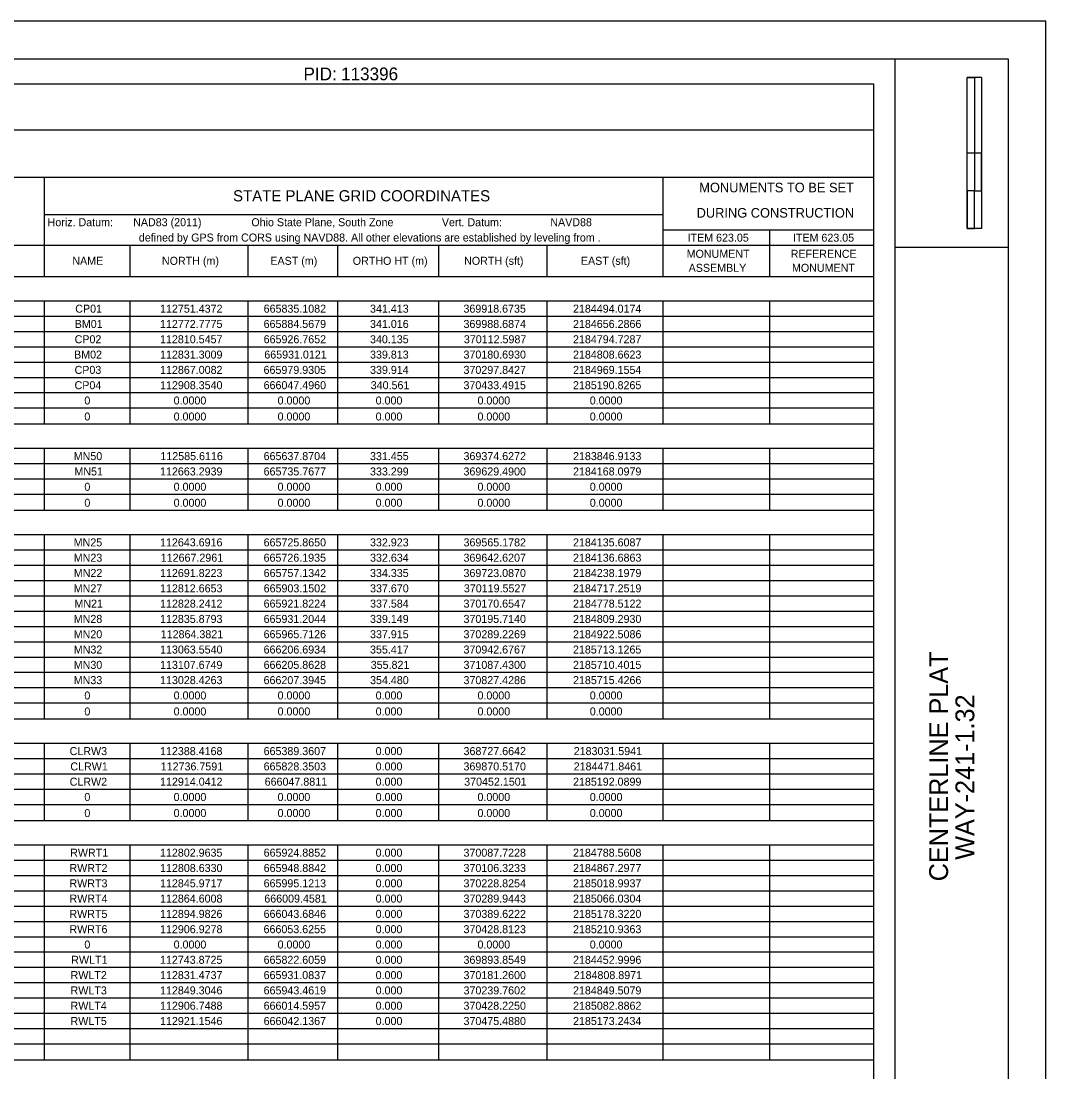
# Model space of a CAD drawing. Extents: x 0 to 680, y 0 to 440.
# Drawn here: x 408.1 to 680, y 161.3 to 440 of the extents above; entities that cross this region are included whole.
import ezdxf

# ---------------------------------------------------------------- set-up
doc = ezdxf.new("R2010")
doc.units = 0
for name, color, linetype in [('SH_Border', 7, 'Continuous'), ('SH_Cut_Line', 7, 'Continuous'), ('SH_Data', 7, 'Continuous'), ('SH_Text', 7, 'Continuous')]:
    doc.layers.add(name, color=color, linetype=linetype)

msp = doc.modelspace()

# ---------------------------------------------------------------- linework, layer by layer
at = {"layer": 'SH_Border'}
for p, q in [((640, 10), (640, 430)), ((640, 380), (670, 380))]:
    msp.add_line(p, q, dxfattribs=at)
msp.add_lwpolyline([(30, 430), (670, 430), (670, 10), (30, 10)], close=True, dxfattribs=at)
at = {"layer": 'SH_Cut_Line'}
msp.add_lwpolyline([(0, 0), (680, 0), (680, 440), (0, 440)], close=True, dxfattribs=at)
at = {"layer": 'SH_Data'}
for p, q in [((659.13, 385), (659.13, 425)), ((662.88, 425), (659.13, 425)), ((659.13, 405), (659.13, 425)), ((659.13, 425), (661, 425)), ((661, 425), (661.02, 425)), ((661.02, 425), (661.02, 405)), ((662.88, 425), (662.88, 385)), ((661.02, 405), (659.13, 405)), ((662.87, 405), (661, 405)), ((661, 405), (661, 395)), ((662.87, 395), (662.87, 405)), ((661, 395), (659.13, 395)), ((659.13, 395), (659.13, 385)), ((661, 395), (662.87, 395)), ((661, 385), (661, 395)), ((662.88, 385), (659.13, 385)), ((659.13, 385), (661, 385))]:
    msp.add_line(p, q, dxfattribs=at)
at = {"layer": 'SH_Text'}
for p, q in [((231.79, 423.36), (436.91, 423.36)), ((436.91, 423.36), (634.27, 423.36)), ((634.27, 423.36), (634.27, 398.64)), ((259.46, 411.19), (436.91, 411.19)), ((436.91, 411.19), (634.27, 411.19)), ((259.46, 398.64), (436.91, 398.64)), ((414.22, 398.64), (414.22, 380.57)), ((436.91, 398.64), (634.27, 398.64)), ((578.38, 398.64), (578.38, 380.57)), ((634.27, 398.64), (634.27, 380.57)), ((414.22, 388.68), (436.91, 388.68)), ((436.91, 388.68), (578.38, 388.68)), ((578.38, 384.62), (634.27, 384.62)), ((606.61, 384.62), (606.61, 380.57)), ((231.79, 380.57), (436.91, 380.57)), ((414.22, 380.57), (414.22, 372.27)), ((436.91, 380.57), (634.27, 380.57)), ((436.91, 380.57), (436.91, 372.27)), ((468.27, 380.57), (468.27, 372.27)), ((492.06, 380.57), (492.06, 372.27)), ((518.81, 380.57), (518.81, 372.27)), ((547.58, 380.57), (547.58, 372.27)), ((578.38, 380.57), (578.38, 372.27)), ((606.61, 380.57), (606.61, 372.27)), ((634.27, 380.57), (634.27, 349.58)), ((231.79, 372.27), (436.91, 372.27)), ((436.91, 372.27), (634.27, 372.27)), ((231.79, 365.81), (436.91, 365.81)), ((414.22, 365.81), (414.22, 349.58)), ((436.91, 365.81), (634.27, 365.81)), ((436.91, 365.81), (436.91, 349.58)), ((468.27, 365.81), (468.27, 349.58)), ((492.06, 365.81), (492.06, 349.58)), ((518.81, 365.81), (518.81, 349.58)), ((547.58, 365.81), (547.58, 349.58)), ((578.38, 365.81), (578.38, 349.58)), ((606.61, 365.81), (606.61, 349.58)), ((231.79, 361.75), (436.91, 361.75)), ((436.91, 361.75), (634.27, 361.75)), ((231.79, 357.69), (436.91, 357.69)), ((436.91, 357.69), (634.27, 357.69)), ((231.79, 353.64), (436.91, 353.64)), ((436.91, 353.64), (634.27, 353.64)), ((231.79, 349.58), (436.91, 349.58)), ((414.22, 349.58), (414.22, 345.52)), ((436.91, 349.58), (634.27, 349.58)), ((436.91, 349.58), (436.91, 345.52)), ((468.27, 349.58), (468.27, 345.52)), ((492.06, 349.58), (492.06, 345.52)), ((518.81, 349.58), (518.81, 345.52)), ((547.58, 349.58), (547.58, 345.52)), ((578.38, 349.58), (578.38, 345.52)), ((606.61, 349.58), (606.61, 345.52)), ((634.27, 349.58), (634.27, 345.52)), ((231.79, 345.52), (436.91, 345.52)), ((414.22, 345.52), (414.22, 333.16)), ((436.91, 345.52), (634.27, 345.52)), ((436.91, 345.52), (436.91, 333.16)), ((468.27, 345.52), (468.27, 333.16)), ((492.06, 345.52), (492.06, 333.16)), ((518.81, 345.52), (518.81, 333.16)), ((547.58, 345.52), (547.58, 333.16)), ((578.38, 345.52), (578.38, 333.16)), ((606.61, 345.52), (606.61, 333.16)), ((634.27, 345.52), (634.27, 267.31)), ((231.79, 341.46), (436.91, 341.46)), ((436.91, 341.46), (634.27, 341.46)), ((231.79, 337.4), (436.91, 337.4)), ((436.91, 337.4), (634.27, 337.4)), ((231.79, 333.16), (436.91, 333.16)), ((436.91, 333.16), (634.27, 333.16)), ((231.79, 326.71), (436.91, 326.71)), ((414.22, 326.71), (414.22, 310.29)), ((436.91, 326.71), (634.27, 326.71)), ((436.91, 326.71), (436.91, 310.29)), ((468.27, 326.71), (468.27, 310.29)), ((492.06, 326.71), (492.06, 310.29)), ((518.81, 326.71), (518.81, 310.29)), ((547.58, 326.71), (547.58, 310.29)), ((578.38, 326.71), (578.38, 310.29)), ((606.61, 326.71), (606.61, 310.29)), ((231.79, 322.65), (436.91, 322.65)), ((436.91, 322.65), (634.27, 322.65)), ((231.79, 318.59), (436.91, 318.59)), ((436.91, 318.59), (634.27, 318.59)), ((231.79, 314.53), (436.91, 314.53)), ((436.91, 314.53), (634.27, 314.53)), ((231.79, 310.29), (436.91, 310.29)), ((436.91, 310.29), (634.27, 310.29)), ((231.79, 303.83), (436.91, 303.83)), ((414.22, 303.83), (414.22, 267.31)), ((436.91, 303.83), (634.27, 303.83)), ((436.91, 303.83), (436.91, 267.31)), ((468.27, 303.83), (468.27, 267.31)), ((492.06, 303.83), (492.06, 267.31)), ((518.81, 303.83), (518.81, 267.31)), ((547.58, 303.83), (547.58, 267.31)), ((578.38, 303.83), (578.38, 267.31)), ((606.61, 303.83), (606.61, 267.31)), ((231.79, 299.78), (436.91, 299.78)), ((436.91, 299.78), (634.27, 299.78)), ((231.79, 295.72), (436.91, 295.72)), ((436.91, 295.72), (634.27, 295.72)), ((231.79, 291.66), (436.91, 291.66)), ((436.91, 291.66), (634.27, 291.66)), ((231.79, 287.6), (436.91, 287.6)), ((436.91, 287.6), (634.27, 287.6)), ((231.79, 283.54), (436.91, 283.54)), ((436.91, 283.54), (634.27, 283.54)), ((231.79, 279.49), (436.91, 279.49)), ((436.91, 279.49), (634.27, 279.49)), ((231.79, 275.43), (436.91, 275.43)), ((436.91, 275.43), (634.27, 275.43)), ((231.79, 271.37), (436.91, 271.37)), ((436.91, 271.37), (634.27, 271.37)), ((231.79, 267.31), (436.91, 267.31)), ((414.22, 267.31), (414.22, 263.25)), ((436.91, 267.31), (634.27, 267.31)), ((436.91, 267.31), (436.91, 263.25)), ((468.27, 267.31), (468.27, 263.25)), ((492.06, 267.31), (492.06, 263.25)), ((518.81, 267.31), (518.81, 263.25)), ((547.58, 267.31), (547.58, 263.25)), ((578.38, 267.31), (578.38, 263.25)), ((606.61, 267.31), (606.61, 263.25)), ((634.27, 267.31), (634.27, 263.25)), ((231.79, 263.25), (436.91, 263.25)), ((414.22, 263.25), (414.22, 254.95)), ((436.91, 263.25), (634.27, 263.25)), ((436.91, 263.25), (436.91, 254.95)), ((468.27, 263.25), (468.27, 254.95)), ((492.06, 263.25), (492.06, 254.95)), ((518.81, 263.25), (518.81, 254.95)), ((547.58, 263.25), (547.58, 254.95)), ((578.38, 263.25), (578.38, 254.95)), ((606.61, 263.25), (606.61, 254.95)), ((634.27, 263.25), (634.27, 240.38)), ((231.79, 259.2), (436.91, 259.2)), ((436.91, 259.2), (634.27, 259.2)), ((231.79, 254.95), (436.91, 254.95)), ((436.91, 254.95), (634.27, 254.95)), ((231.79, 248.5), (436.91, 248.5)), ((414.22, 248.5), (414.22, 240.38)), ((436.91, 248.5), (634.27, 248.5)), ((436.91, 248.5), (436.91, 240.38)), ((468.27, 248.5), (468.27, 240.38)), ((492.06, 248.5), (492.06, 240.38)), ((518.81, 248.5), (518.81, 240.38)), ((547.58, 248.5), (547.58, 240.38)), ((578.38, 248.5), (578.38, 240.38)), ((606.61, 248.5), (606.61, 240.38)), ((231.79, 244.44), (436.91, 244.44)), ((436.91, 244.44), (634.27, 244.44)), ((231.79, 240.38), (436.91, 240.38)), ((414.22, 240.38), (414.22, 236.32)), ((436.91, 240.38), (634.27, 240.38)), ((436.91, 240.38), (436.91, 236.32)), ((468.27, 240.38), (468.27, 236.32)), ((492.06, 240.38), (492.06, 236.32)), ((518.81, 240.38), (518.81, 236.32)), ((547.58, 240.38), (547.58, 236.32)), ((578.38, 240.38), (578.38, 236.32)), ((606.61, 240.38), (606.61, 236.32)), ((634.27, 240.38), (634.27, 236.32)), ((231.79, 236.32), (436.91, 236.32)), ((414.22, 236.32), (414.22, 232.26)), ((436.91, 236.32), (634.27, 236.32)), ((436.91, 236.32), (436.91, 232.26)), ((468.27, 236.32), (468.27, 232.26)), ((492.06, 236.32), (492.06, 232.26)), ((518.81, 236.32), (518.81, 232.26)), ((547.58, 236.32), (547.58, 232.26)), ((578.38, 236.32), (578.38, 232.26)), ((606.61, 236.32), (606.61, 232.26)), ((634.27, 236.32), (634.27, 232.26)), ((231.79, 232.26), (436.91, 232.26)), ((414.22, 232.26), (414.22, 228.02)), ((436.91, 232.26), (634.27, 232.26)), ((436.91, 232.26), (436.91, 228.02)), ((468.27, 232.26), (468.27, 228.02)), ((492.06, 232.26), (492.06, 228.02)), ((518.81, 232.26), (518.81, 228.02)), ((547.58, 232.26), (547.58, 228.02)), ((578.38, 232.26), (578.38, 228.02)), ((606.61, 232.26), (606.61, 228.02)), ((634.27, 232.26), (634.27, 228.02)), ((231.79, 228.02), (436.91, 228.02)), ((436.91, 228.02), (634.27, 228.02)), ((634.27, 228.02), (634.27, 217.51)), ((231.79, 221.57), (436.91, 221.57)), ((414.22, 221.57), (414.22, 217.51)), ((436.91, 221.57), (634.27, 221.57)), ((436.91, 221.57), (436.91, 217.51)), ((468.27, 221.57), (468.27, 217.51)), ((492.06, 221.57), (492.06, 217.51)), ((518.81, 221.57), (518.81, 217.51)), ((547.58, 221.57), (547.58, 217.51)), ((578.38, 221.57), (578.38, 217.51)), ((606.61, 221.57), (606.61, 217.51)), ((231.79, 217.51), (436.91, 217.51)), ((414.22, 217.51), (414.22, 164.57)), ((436.91, 217.51), (634.27, 217.51)), ((436.91, 217.51), (436.91, 164.57)), ((468.27, 217.51), (468.27, 164.57)), ((492.06, 217.51), (492.06, 164.57)), ((518.81, 217.51), (518.81, 164.57)), ((547.58, 217.51), (547.58, 164.57)), ((578.38, 217.51), (578.38, 164.57)), ((606.61, 217.51), (606.61, 164.57)), ((634.27, 217.51), (634.27, 113.48)), ((231.79, 213.45), (436.91, 213.45)), ((436.91, 213.45), (634.27, 213.45)), ((231.79, 209.39), (436.91, 209.39)), ((436.91, 209.39), (634.27, 209.39)), ((231.79, 205.33), (436.91, 205.33)), ((436.91, 205.33), (634.27, 205.33)), ((231.79, 201.28), (436.91, 201.28)), ((436.91, 201.28), (634.27, 201.28)), ((231.79, 197.22), (436.91, 197.22)), ((436.91, 197.22), (634.27, 197.22)), ((231.79, 193.16), (436.91, 193.16)), ((436.91, 193.16), (634.27, 193.16)), ((231.79, 189.1), (436.91, 189.1)), ((436.91, 189.1), (634.27, 189.1)), ((231.79, 185.04), (436.91, 185.04)), ((436.91, 185.04), (634.27, 185.04)), ((231.79, 180.99), (436.91, 180.99)), ((436.91, 180.99), (634.27, 180.99)), ((231.79, 176.93), (436.91, 176.93)), ((436.91, 176.93), (634.27, 176.93)), ((231.79, 172.87), (436.91, 172.87)), ((436.91, 172.87), (634.27, 172.87)), ((231.79, 168.81), (436.91, 168.81)), ((436.91, 168.81), (634.27, 168.81)), ((231.79, 164.57), (436.91, 164.57)), ((436.91, 164.57), (634.27, 164.57))]:
    msp.add_line(p, q, dxfattribs=at)

# ---------------------------------------------------------------- texts
at = {"layer": 'SH_Data'}
for s, p in [('CENTERLINE PLAT', (654.02, 211.9)), ('WAY-241-1.32', (660.98, 217.6))]:
    msp.add_text(s, height=5, rotation=90, dxfattribs=at).set_placement(p)
at = {"layer": 'SH_Text'}
for s, height, p in [('PID:', 3.394, (483.02, 424.28)), ('113396', 3.394, (492.98, 424.28)), ('  MONUMENTS TO BE SET', 2.5455, (586.12, 394.58)), ('STATE PLANE GRID COORDINATES', 2.9697, (464.34, 392.18)), (' DURING CONSTRUCTION', 2.5455, (586.36, 387.87)), ('Horiz. Datum:', 2.1212, (415.14, 385.59)), ('NAD83 (2011)', 2.1212, (437.83, 385.59)), ('Ohio State Plane, South Zone', 2.1212, (469.19, 385.59)), ('Vert. Datum:', 2.1212, (519.73, 385.59)), ('NAVD88', 2.121, (548.5, 385.59)), (' defined by GPS from CORS using NAVD88. All other elevations are established by leveling from .', 2.1212, (438.56, 381.53)), ('ITEM 623.05', 2.1212, (584.91, 381.49)), ('ITEM 623.05', 2.1212, (612.86, 381.49)), ('MONUMENT ', 2.121, (584.67, 377.21)), ('REFERENCE ', 2.121, (612.28, 377.21)), ('NAME', 2.121, (421.7, 375.36)), ('NORTH (m)', 2.121, (445.47, 375.36)), ('EAST (m)', 2.121, (474.23, 375.36)), ('ORTHO HT (m)', 2.1212, (496.09, 375.36)), ('NORTH (sft)', 2.1212, (525.63, 375.36)), ('EAST (sft)', 2.121, (556.61, 375.36)), ('ASSEMBLY', 2.121, (585.2, 373.5)), ('MONUMENT', 2.121, (612.61, 373.5)), ('CP01', 2.121, (422.47, 362.67)), ('112751.4372', 2.1212, (444.97, 362.67)), ('665835.1082', 2.1212, (472.45, 362.67)), ('341.413', 2.121, (500.67, 362.67)), ('369918.6735', 2.1212, (525.46, 362.67)), ('2184494.0174', 2.1212, (554.52, 362.67)), ('BM01', 2.121, (422.33, 358.62)), ('112772.7775', 2.1212, (444.95, 358.62)), ('665884.5679', 2.1212, (472.44, 358.62)), ('341.016', 2.121, (500.67, 358.62)), ('369988.6874', 2.1212, (525.47, 358.62)), ('2184656.2866', 2.1212, (554.52, 358.62)), ('CP02', 2.121, (422.3, 354.56)), ('112810.5457', 2.1212, (444.96, 354.56)), ('665926.7652', 2.1212, (472.45, 354.56)), ('340.135', 2.121, (500.67, 354.56)), ('370112.5987', 2.1212, (525.57, 354.56)), ('2184794.7287', 2.1212, (554.52, 354.56)), ('BM02', 2.121, (422.15, 350.5)), ('112831.3009', 2.1212, (444.96, 350.5)), ('665931.0121', 2.1212, (472.62, 350.5)), ('339.813', 2.121, (500.67, 350.5)), ('370180.6930', 2.1212, (525.47, 350.5)), ('2184808.6623', 2.1212, (554.52, 350.5)), ('CP03', 2.121, (422.29, 346.44)), ('112867.0082', 2.1212, (444.97, 346.44)), ('665979.9305', 2.1212, (472.43, 346.44)), ('339.914', 2.121, (500.68, 346.44)), ('370297.8427', 2.1212, (525.47, 346.44)), ('2184969.1554', 2.1212, (554.52, 346.44)), ('CP04', 2.121, (422.29, 342.38)), ('112908.3540', 2.1212, (444.97, 342.38)), ('666047.4960', 2.1212, (472.44, 342.38)), ('340.561', 2.121, (500.86, 342.38)), ('370433.4915', 2.1212, (525.46, 342.38)), ('2185190.8265', 2.1212, (554.51, 342.38)), ('0', 2.12, (424.89, 338.33)), ('0.0000', 2.121, (448.57, 338.33)), ('0.0000', 2.121, (476.15, 338.33)), ('0.000', 2.121, (502.16, 338.33)), ('0.0000', 2.121, (529.18, 338.33)), ('0.0000', 2.121, (558.97, 338.33)), ('0', 2.12, (424.89, 334.08)), ('0.0000', 2.121, (448.57, 334.08)), ('0.0000', 2.121, (476.15, 334.08)), ('0.000', 2.121, (502.16, 334.08)), ('0.0000', 2.121, (529.18, 334.08)), ('0.0000', 2.121, (558.97, 334.08)), ('MN50', 2.121, (422.07, 323.57)), ('112585.6116', 2.1212, (445.06, 323.57)), ('665637.8704', 2.1212, (472.44, 323.57)), ('331.455', 2.121, (500.67, 323.57)), ('369374.6272', 2.1212, (525.48, 323.57)), ('2183846.9133', 2.1212, (554.52, 323.57)), ('MN51', 2.121, (422.25, 319.51)), ('112663.2939', 2.1212, (444.96, 319.51)), ('665735.7677', 2.1212, (472.44, 319.51)), ('333.299', 2.121, (500.67, 319.51)), ('369629.4900', 2.1212, (525.47, 319.51)), ('2184168.0979', 2.1212, (554.52, 319.51)), ('0', 2.12, (424.89, 315.45)), ('0.0000', 2.121, (448.57, 315.45)), ('0.0000', 2.121, (476.15, 315.45)), ('0.000', 2.121, (502.16, 315.45)), ('0.0000', 2.121, (529.18, 315.45)), ('0.0000', 2.121, (558.97, 315.45)), ('0', 2.12, (424.89, 311.21)), ('0.0000', 2.121, (448.57, 311.21)), ('0.0000', 2.121, (476.15, 311.21)), ('0.000', 2.121, (502.16, 311.21)), ('0.0000', 2.121, (529.18, 311.21)), ('0.0000', 2.121, (558.97, 311.21)), ('MN25', 2.121, (422.06, 300.7)), ('112643.6916', 2.1212, (444.96, 300.7)), ('665725.8650', 2.1212, (472.44, 300.7)), ('332.923', 2.121, (500.67, 300.7)), ('369565.1782', 2.1212, (525.48, 300.7)), ('2184135.6087', 2.1212, (554.52, 300.7)), ('MN23', 2.121, (422.07, 296.64)), ('112667.2961', 2.1212, (445.15, 296.64)), ('665726.1935', 2.1212, (472.43, 296.64)), ('332.634', 2.121, (500.68, 296.64)), ('369642.6207', 2.1212, (525.47, 296.64)), ('2184136.6863', 2.1212, (554.52, 296.64)), ('MN22', 2.121, (422.08, 292.58)), ('112691.8223', 2.1212, (444.96, 292.58)), ('665757.1342', 2.1212, (472.45, 292.58)), ('334.335', 2.121, (500.67, 292.58)), ('369723.0870', 2.1212, (525.47, 292.58)), ('2184238.1979', 2.1212, (554.52, 292.58)), ('MN27', 2.121, (422.07, 288.52)), ('112812.6653', 2.1212, (444.96, 288.52)), ('665903.1502', 2.1212, (472.45, 288.52)), ('337.670', 2.121, (500.68, 288.52)), ('370119.5527', 2.1212, (525.57, 288.52)), ('2184717.2519', 2.1212, (554.52, 288.52)), ('MN21', 2.121, (422.25, 284.47)), ('112828.2412', 2.1212, (444.97, 284.47)), ('665921.8224', 2.1212, (472.44, 284.47)), ('337.584', 2.121, (500.68, 284.47)), ('370170.6547', 2.1212, (525.47, 284.47)), ('2184778.5122', 2.1212, (554.53, 284.47)), ('MN28', 2.121, (422.07, 280.41)), ('112835.8793', 2.1212, (444.96, 280.41)), ('665931.2044', 2.1212, (472.44, 280.41)), ('339.149', 2.121, (500.67, 280.41)), ('370195.7140', 2.1212, (525.47, 280.41)), ('2184809.2930', 2.1212, (554.52, 280.41)), ('MN20', 2.121, (422.07, 276.35)), ('112864.3821', 2.1212, (445.15, 276.35)), ('665965.7126', 2.1212, (472.44, 276.35)), ('337.915', 2.121, (500.67, 276.35)), ('370289.2269', 2.1212, (525.47, 276.35)), ('2184922.5086', 2.1212, (554.52, 276.35)), ('MN32', 2.121, (422.08, 272.29)), ('113063.5540', 2.1212, (444.97, 272.29)), ('666206.6934', 2.1212, (472.44, 272.29)), ('355.417', 2.121, (500.67, 272.29)), ('370942.6767', 2.1212, (525.47, 272.29)), ('2185713.1265', 2.1212, (554.51, 272.29)), ('MN30', 2.121, (422.07, 268.23)), ('113107.6749', 2.1212, (444.96, 268.23)), ('666205.8628', 2.1212, (472.44, 268.23)), ('355.821', 2.121, (500.86, 268.23)), ('371087.4300', 2.1212, (525.47, 268.23)), ('2185710.4015', 2.1212, (554.51, 268.23)), ('MN33', 2.121, (422.07, 264.18)), ('113028.4263', 2.1212, (444.96, 264.18)), ('666207.3945', 2.1212, (472.43, 264.18)), ('354.480', 2.121, (500.68, 264.18)), ('370827.4286', 2.1212, (525.47, 264.18)), ('2185715.4266', 2.1212, (554.52, 264.18)), ('0', 2.12, (424.89, 260.12)), ('0.0000', 2.121, (448.57, 260.12)), ('0.0000', 2.121, (476.15, 260.12)), ('0.000', 2.121, (502.16, 260.12)), ('0.0000', 2.121, (529.18, 260.12)), ('0.0000', 2.121, (558.97, 260.12)), ('0', 2.12, (424.89, 255.88)), ('0.0000', 2.121, (448.57, 255.88)), ('0.0000', 2.121, (476.15, 255.88)), ('0.000', 2.121, (502.16, 255.88)), ('0.0000', 2.121, (529.18, 255.88)), ('0.0000', 2.121, (558.97, 255.88)), ('CLRW3', 2.121, (420.98, 245.36)), ('112388.4168', 2.1212, (444.96, 245.36)), ('665389.3607', 2.1212, (472.44, 245.36)), ('0.000', 2.121, (502.16, 245.36)), ('368727.6642', 2.1212, (525.48, 245.36)), ('2183031.5941', 2.1212, (554.7, 245.36)), ('CLRW1', 2.121, (421.17, 241.3)), ('112736.7591', 2.1212, (445.15, 241.3)), ('665828.3503', 2.1212, (472.44, 241.3)), ('0.000', 2.121, (502.16, 241.3)), ('369870.5170', 2.1212, (525.47, 241.3)), ('2184471.8461', 2.1212, (554.7, 241.3)), ('CLRW2', 2.121, (420.99, 237.25)), ('112914.0412', 2.1212, (444.97, 237.25)), ('666047.8811', 2.1212, (472.72, 237.25)), ('0.000', 2.121, (502.16, 237.25)), ('370452.1501', 2.1212, (525.65, 237.25)), ('2185192.0899', 2.1212, (554.52, 237.25)), ('0', 2.12, (424.89, 233.19)), ('0.0000', 2.121, (448.57, 233.19)), ('0.0000', 2.121, (476.15, 233.19)), ('0.000', 2.121, (502.16, 233.19)), ('0.0000', 2.121, (529.18, 233.19)), ('0.0000', 2.121, (558.97, 233.19)), ('0', 2.12, (424.89, 228.94)), ('0.0000', 2.121, (448.57, 228.94)), ('0.0000', 2.121, (476.15, 228.94)), ('0.000', 2.121, (502.16, 228.94)), ('0.0000', 2.121, (529.18, 228.94)), ('0.0000', 2.121, (558.97, 228.94)), ('RWRT1', 2.121, (421.12, 218.43)), ('112802.9635', 2.1212, (444.95, 218.43)), ('665924.8852', 2.1212, (472.45, 218.43)), ('0.000', 2.121, (502.16, 218.43)), ('370087.7228', 2.1212, (525.47, 218.43)), ('2184788.5608', 2.1212, (554.52, 218.43)), ('RWRT2', 2.121, (420.94, 214.37)), ('112808.6330', 2.1212, (444.97, 214.37)), ('665948.8842', 2.1212, (472.45, 214.37)), ('0.000', 2.121, (502.16, 214.37)), ('370106.3233', 2.1212, (525.47, 214.37)), ('2184867.2977', 2.1212, (554.52, 214.37)), ('RWRT3', 2.121, (420.93, 210.31)), ('112845.9717', 2.1212, (444.96, 210.31)), ('665995.1213', 2.1212, (472.44, 210.31)), ('0.000', 2.121, (502.16, 210.31)), ('370228.8254', 2.1212, (525.47, 210.31)), ('2185018.9937', 2.1212, (554.52, 210.31)), ('RWRT4', 2.121, (420.94, 206.26)), ('112864.6008', 2.1212, (444.96, 206.26)), ('666009.4581', 2.1212, (472.62, 206.26)), ('0.000', 2.121, (502.16, 206.26)), ('370289.9443', 2.1212, (525.47, 206.26)), ('2185066.0304', 2.1212, (554.52, 206.26)), ('RWRT5', 2.121, (420.92, 202.2)), ('112894.9826', 2.1212, (444.96, 202.2)), ('666043.6846', 2.1212, (472.44, 202.2)), ('0.000', 2.121, (502.16, 202.2)), ('370389.6222', 2.1212, (525.48, 202.2)), ('2185178.3220', 2.1212, (554.52, 202.2)), ('RWRT6', 2.121, (420.93, 198.14)), ('112906.9278', 2.1212, (444.96, 198.14)), ('666053.6255', 2.1212, (472.43, 198.14)), ('0.000', 2.121, (502.16, 198.14)), ('370428.8123', 2.1212, (525.47, 198.14)), ('2185210.9363', 2.1212, (554.52, 198.14)), ('0', 2.12, (424.89, 194.08)), ('0.0000', 2.121, (448.57, 194.08)), ('0.0000', 2.121, (476.15, 194.08)), ('0.000', 2.121, (502.16, 194.08)), ('0.0000', 2.121, (529.18, 194.08)), ('0.0000', 2.121, (558.97, 194.08)), ('RWLT1', 2.121, (421.41, 190.02)), ('112743.8725', 2.1212, (444.95, 190.02)), ('665822.6059', 2.1212, (472.44, 190.02)), ('0.000', 2.121, (502.16, 190.02)), ('369893.8549', 2.1212, (525.47, 190.02)), ('2184452.9996', 2.1212, (554.52, 190.02)), ('RWLT2', 2.121, (421.24, 185.97)), ('112831.4737', 2.1212, (444.96, 185.97)), ('665931.0837', 2.1212, (472.44, 185.97)), ('0.000', 2.121, (502.16, 185.97)), ('370181.2600', 2.1212, (525.47, 185.97)), ('2184808.8971', 2.1212, (554.7, 185.97)), ('RWLT3', 2.121, (421.23, 181.91)), ('112849.3046', 2.1212, (444.96, 181.91)), ('665943.4619', 2.1212, (472.44, 181.91)), ('0.000', 2.121, (502.16, 181.91)), ('370239.7602', 2.1212, (525.48, 181.91)), ('2184849.5079', 2.1212, (554.52, 181.91)), ('RWLT4', 2.121, (421.23, 177.85)), ('112906.7488', 2.1212, (444.96, 177.85)), ('666014.5957', 2.1212, (472.44, 177.85)), ('0.000', 2.121, (502.16, 177.85)), ('370428.2250', 2.1212, (525.47, 177.85)), ('2185082.8862', 2.1212, (554.53, 177.85)), ('RWLT5', 2.121, (421.22, 173.79)), ('112921.1546', 2.1212, (444.96, 173.79)), ('666042.1367', 2.1212, (472.44, 173.79)), ('0.000', 2.121, (502.16, 173.79)), ('370475.4880', 2.1212, (525.47, 173.79)), ('2185173.2434', 2.1212, (554.52, 173.79))]:
    msp.add_text(s, height=height, dxfattribs=at).set_placement(p)

doc.saveas('drawing.dxf')
